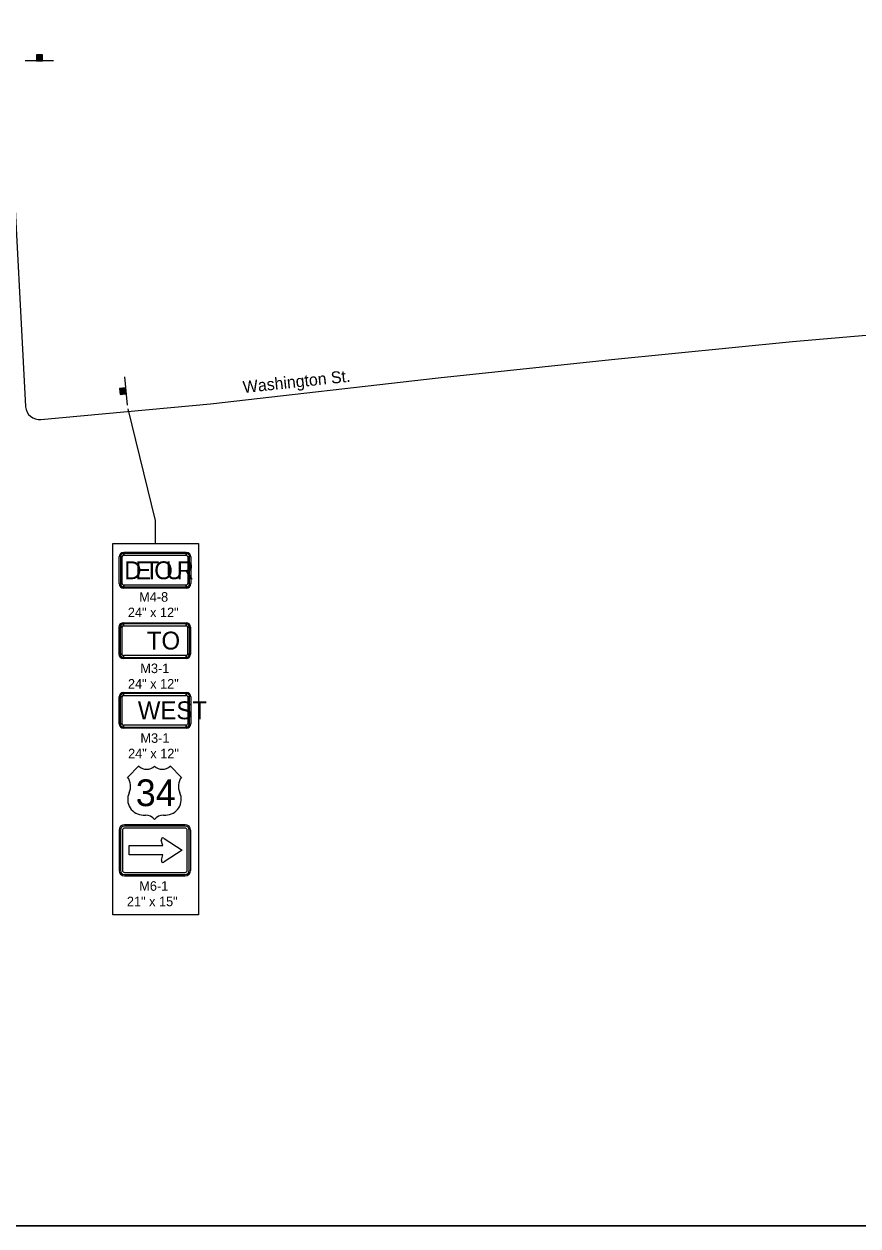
# Model space of a CAD drawing. Extents: x 10133 to 81668, y 6132 to 11018.
# Drawn here: x 10817 to 11517, y 7924 to 8934 of the extents above; entities that cross this region are included whole.
import ezdxf

# ---------------------------------------------------------------- set-up
doc = ezdxf.new("R2010")
doc.units = 0
for name, color, linetype in [('dsnTextFinalPlan', 7, 'Continuous'), ('Level 10', 7, 'Continuous'), ('Level 2', 7, 'Continuous'), ('Level 4', 7, 'Continuous'), ('Level 5', 7, 'Continuous'), ('SheetBorder', 7, 'Continuous'), ('SheetText', 7, 'Continuous')]:
    doc.layers.add(name, color=color, linetype=linetype)

msp = doc.modelspace()

# ---------------------------------------------------------------- linework, layer by layer
at = {"layer": 'dsnTextFinalPlan'}
for p, q in [((10841.4, 8903.1), (10817.4, 8903.1)), ((10832, 8907.8), (10827.1, 8907.8)), ((10827.1, 8907.5), (10832, 8907.5)), ((10832, 8907.3), (10827.1, 8907.3)), ((10827.1, 8907), (10832, 8907)), ((10832, 8906.8), (10827.1, 8906.8)), ((10827.1, 8906.4), (10832, 8906.4)), ((10832, 8906.3), (10827.1, 8906.3)), ((10827.1, 8905.9), (10832, 8905.9)), ((10832, 8905.6), (10827.1, 8905.5)), ((10827.1, 8905.3), (10832, 8905.3)), ((10832, 8905.1), (10827.1, 8905.1)), ((10827.1, 8904.8), (10832, 8904.9)), ((10832, 8904.6), (10827.1, 8904.6)), ((10827.1, 8904.4), (10832, 8904.4)), ((10832, 8904.2), (10827.1, 8904.2)), ((10827.1, 8903.9), (10832, 8904)), ((10832, 8903.7), (10827.1, 8903.7)), ((10827.1, 8903.5), (10832, 8903.5)), ((10900.9, 8637.6), (10903.2, 8613.7)), ((10897.2, 8627.7), (10897.7, 8622.8)), ((10897.9, 8622.9), (10897.5, 8627.7)), ((10897.7, 8627.7), (10898.1, 8622.9)), ((10898.4, 8622.9), (10897.9, 8627.8)), ((10898.1, 8627.8), (10898.6, 8622.9)), ((10899, 8623), (10898.5, 8627.8)), ((10898.7, 8627.8), (10899.2, 8623)), ((10899.5, 8623), (10899.1, 8627.9)), ((10899.4, 8627.9), (10899.9, 8623)), ((10900.1, 8623.1), (10899.7, 8627.9)), ((10899.9, 8627.9), (10900.3, 8623.1)), ((10900.6, 8623.1), (10900.1, 8628)), ((10900.4, 8628), (10900.9, 8623.1)), ((10901, 8623.2), (10900.6, 8628)), ((10900.7, 8628), (10901.2, 8623.2)), ((10901.5, 8623.2), (10901, 8628.1)), ((10901.2, 8628.1), (10901.7, 8623.2)), ((10901.9, 8623.2), (10901.5, 8628.1)), ((10830.8, 8601.8), (10973.3, 8615))]:
    msp.add_line(p, q, dxfattribs=at)
for points in [[(10785.1, 9142), (10794.6, 9051.1), (10817.8, 8612.5)], [(10973.3, 8615), (11164.6, 8636.6), (11310.1, 8652.1), (11462.4, 8667.2), (11586.1, 8678), (11684.7, 8691.3), (11805.7, 8706), (11965.7, 8718.9)], [(10927.1, 8497.6), (10927.1, 8516.9), (10904, 8610.6)]]:
    msp.add_lwpolyline(points, dxfattribs=at)
for points in [[(10827.1, 8903.2), (10832, 8903.2), (10832, 8908.1), (10827.1, 8908.1)], [(10902.2, 8623.3), (10901.7, 8628.2), (10896.8, 8627.7), (10897.3, 8622.8)], [(10891.1, 8497.6), (10963.2, 8497.6), (10963.2, 8185.4), (10891.1, 8185.4)], [(10891.1, 8497.6), (10963.2, 8497.6), (10963.2, 8185.4), (10891.1, 8185.4)]]:
    msp.add_lwpolyline(points, close=True, dxfattribs=at)
msp.add_arc((10829.7, 8613.7), 12, 185.8975, 275.3136, dxfattribs=at)
at = {"layer": 'Level 10'}
for p, q in [((10896.5, 8463.8), (10896.5, 8486.3)), ((10897.5, 8486.3), (10899, 8486.3)), ((10900.3, 8490.1), (10952.9, 8490.1)), ((10900.3, 8487.6), (10900.3, 8489.1)), ((10952.9, 8489.1), (10952.9, 8487.6)), ((10954.2, 8486.3), (10955.7, 8486.3)), ((10956.7, 8486.3), (10956.7, 8463.8)), ((10899, 8463.8), (10897.5, 8463.8)), ((10900.3, 8461), (10900.3, 8462.5)), ((10952.9, 8460), (10900.3, 8460)), ((10952.9, 8462.5), (10952.9, 8461)), ((10955.7, 8463.8), (10954.2, 8463.8)), ((10896.4, 8404.6), (10896.4, 8427.2)), ((10897.3, 8427.2), (10898.9, 8427.2)), ((10900.1, 8430.9), (10952.8, 8430.9)), ((10900.1, 8428.4), (10900.1, 8430)), ((10952.8, 8430), (10952.8, 8428.4)), ((10954, 8427.2), (10955.6, 8427.2)), ((10956.5, 8427.2), (10956.5, 8404.6)), ((10898.9, 8404.6), (10897.3, 8404.6)), ((10900.1, 8401.8), (10900.1, 8403.4)), ((10952.8, 8403.4), (10952.8, 8401.8)), ((10955.6, 8404.6), (10954, 8404.6)), ((10952.8, 8400.9), (10900.1, 8400.9)), ((10896.5, 8346.1), (10896.5, 8368.6)), ((10897.4, 8368.6), (10899, 8368.6)), ((10900.2, 8372.4), (10952.9, 8372.4)), ((10900.2, 8369.9), (10900.2, 8371.4)), ((10952.9, 8371.4), (10952.9, 8369.9)), ((10954.1, 8368.6), (10955.7, 8368.6)), ((10956.6, 8368.6), (10956.6, 8346.1)), ((10899, 8346.1), (10897.4, 8346.1)), ((10900.2, 8343.3), (10900.2, 8344.8)), ((10952.9, 8344.8), (10952.9, 8343.3)), ((10955.7, 8346.1), (10954.1, 8346.1)), ((10952.9, 8342.3), (10900.2, 8342.3)), ((10896.4, 8256.6), (10896.4, 8222.8)), ((10897.6, 8256.6), (10897.6, 8222.8)), ((10899.3, 8256.6), (10899.3, 8222.8)), ((10952, 8261.2), (10901, 8261.2)), ((10952, 8260.1), (10901, 8260.1)), ((10952, 8258.3), (10901, 8258.3)), ((10953.7, 8222.8), (10953.7, 8256.6)), ((10955.4, 8222.8), (10955.4, 8256.6)), ((10956.6, 8222.8), (10956.6, 8256.6)), ((10901, 8221.1), (10952, 8221.1)), ((10901, 8219.4), (10952, 8219.4)), ((10901, 8218.3), (10952, 8218.3))]:
    msp.add_line(p, q, dxfattribs=at)
for points in [[(10897.5, 8486.3), (10897.5, 8463.8), (10899, 8463.8), (10899, 8486.3), (10897.5, 8486.3)], [(10952.9, 8489.1), (10900.3, 8489.1), (10900.3, 8487.6), (10952.9, 8487.6), (10952.9, 8489.1)], [(10955.7, 8463.8), (10955.7, 8486.3), (10954.2, 8486.3), (10954.2, 8463.8), (10955.7, 8463.8)], [(10900.3, 8461), (10952.9, 8461), (10952.9, 8462.5), (10900.3, 8462.5), (10900.3, 8461)], [(10897.3, 8427.2), (10897.3, 8404.6), (10898.9, 8404.6), (10898.9, 8427.2), (10897.3, 8427.2)], [(10952.8, 8430), (10900.1, 8430), (10900.1, 8428.4), (10952.8, 8428.4), (10952.8, 8430)], [(10955.6, 8404.6), (10955.6, 8427.2), (10954, 8427.2), (10954, 8404.6), (10955.6, 8404.6)], [(10900.1, 8401.8), (10952.8, 8401.8), (10952.8, 8403.4), (10900.1, 8403.4), (10900.1, 8401.8)], [(10897.4, 8368.6), (10897.4, 8346.1), (10899, 8346.1), (10899, 8368.6), (10897.4, 8368.6)], [(10952.9, 8371.4), (10900.2, 8371.4), (10900.2, 8369.9), (10952.9, 8369.9), (10952.9, 8371.4)], [(10955.7, 8346.1), (10955.7, 8368.6), (10954.1, 8368.6), (10954.1, 8346.1), (10955.7, 8346.1)], [(10900.2, 8343.3), (10952.9, 8343.3), (10952.9, 8344.8), (10900.2, 8344.8), (10900.2, 8343.3)]]:
    msp.add_lwpolyline(points, close=True, dxfattribs=at)
for points in [[(10932, 8231.3), (10933.3, 8235.9), (10904.8, 8235.9), (10904.8, 8243.6), (10933.3, 8243.6), (10931.9, 8248.2)], [(10934.4, 8249.5), (10949.4, 8239.7), (10934.4, 8229.9)]]:
    msp.add_lwpolyline(points, dxfattribs=at)
for centre, radius, start, end in [((10900.3, 8486.3), 3.76, 90, 180), ((10900.3, 8486.3), 2.82, 90.0002, 179.9998), ((10900.3, 8486.3), 1.25, 90.0002, 179.9998), ((10952.9, 8486.3), 3.76, 0, 90), ((10952.9, 8486.3), 2.82, 0, 90.0002), ((10952.9, 8486.3), 1.25, 0, 90.0002), ((10900.3, 8463.8), 3.76, 180, 270), ((10900.3, 8463.8), 2.82, 179.9998, 270.0001), ((10900.3, 8463.8), 1.25, 179.9998, 270.0001), ((10952.9, 8463.8), 2.82, 270.0001, 0.0003), ((10952.9, 8463.8), 1.25, 270.0001, 0.0003), ((10952.9, 8463.8), 3.76, 270, 359.9911), ((10900.1, 8427.2), 3.76, 90, 180), ((10900.1, 8427.2), 2.82, 90.0002, 179.9998), ((10900.1, 8427.2), 1.25, 90.0002, 179.9998), ((10952.8, 8427.2), 3.76, 0, 90), ((10952.8, 8427.2), 2.82, 0, 90.0002), ((10952.8, 8427.2), 1.25, 0, 90.0002), ((10900.1, 8404.6), 3.76, 180, 270), ((10900.1, 8404.6), 2.82, 179.9998, 270.0001), ((10900.1, 8404.6), 1.25, 179.9998, 270.0001), ((10952.8, 8404.6), 2.82, 270.0001, 0.0003), ((10952.8, 8404.6), 1.25, 270.0001, 0.0003), ((10952.8, 8404.6), 3.76, 270, 359.9911), ((10900.2, 8368.6), 3.76, 90, 180), ((10900.2, 8368.6), 2.82, 90.0002, 179.9998), ((10900.2, 8368.6), 1.25, 90.0002, 179.9998), ((10952.9, 8368.6), 3.76, 0, 90), ((10952.9, 8368.6), 2.82, 0, 90.0002), ((10952.9, 8368.6), 1.25, 0, 90.0002), ((10900.2, 8346.1), 3.76, 180, 270), ((10900.2, 8346.1), 2.82, 179.9998, 270.0001), ((10900.2, 8346.1), 1.25, 179.9998, 270.0001), ((10952.9, 8346.1), 2.82, 270.0001, 0.0003), ((10952.9, 8346.1), 1.25, 270.0001, 0.0003), ((10952.9, 8346.1), 3.76, 270, 359.9911), ((10901, 8256.6), 4.58, 90, 180), ((10901, 8256.6), 3.44, 90, 180), ((10901, 8256.6), 1.72, 90, 180), ((10952, 8256.6), 4.58, 360, 90), ((10952, 8256.6), 3.44, 0, 90), ((10952, 8256.6), 1.72, 0, 90), ((10933.3, 8248.6), 1.43, 56.6109, 195.9691), ((11012.9, 8369.3), 143.2, 236.6109, 236.7714), ((10901, 8222.8), 4.58, 180, 270), ((10901, 8222.8), 3.44, 180, 270), ((10901, 8222.8), 1.72, 180, 270), ((10933.3, 8230.9), 1.4, 164.0309, 303.3104), ((11012.7, 8110.1), 143.2, 123.143, 123.3104), ((10952, 8222.8), 4.58, 270, 0), ((10952, 8222.8), 3.44, 270, 360), ((10952, 8222.8), 1.72, 270, 0)]:
    msp.add_arc(centre, radius, start, end, dxfattribs=at)
at = {"layer": 'Level 4'}
for p, q in [((10913.1, 8310.6), (10903.7, 8301.2)), ((10913.1, 8310.6), (10903.7, 8301.2)), ((10948.7, 8301.2), (10939.3, 8310.6)), ((10948.7, 8301.2), (10939.3, 8310.6)), ((10916.8, 8269.3), (10918.7, 8269.3)), ((10916.8, 8269.3), (10918.7, 8269.3)), ((10933.7, 8269.3), (10935.6, 8269.3)), ((10933.7, 8269.3), (10935.6, 8269.3))]:
    msp.add_line(p, q, dxfattribs=at)
for centre, radius, start, end in [((10919.6, 8317.2), 9.38, 225.5729, 314.4272), ((10919.6, 8317.2), 9.38, 225.5729, 314.4272), ((10932.8, 8317.2), 9.38, 225.5729, 314.4272), ((10932.8, 8317.2), 9.38, 225.5729, 314.4272), ((10893, 8293.5), 13.1, 334.9895, 35.6629), ((10893, 8293.5), 13.1, 334.9895, 35.6629), ((10959.4, 8293.5), 13.1, 144.3372, 205.01), ((10959.4, 8293.5), 13.1, 144.3372, 205.01), ((10916.8, 8282.4), 13.1, 154.9897, 270.0001), ((10916.8, 8282.4), 13.1, 154.9897, 270.0001), ((10935.6, 8282.4), 13.1, 270.0001, 25.0104), ((10935.6, 8282.4), 13.1, 270.0001, 25.0104), ((10918.7, 8259.9), 9.38, 36.8699, 90.0002), ((10918.7, 8259.9), 9.38, 36.8699, 90.0002), ((10933.7, 8259.9), 9.38, 90.0002, 143.13), ((10933.7, 8259.9), 9.38, 90.0002, 143.13)]:
    msp.add_arc(centre, radius, start, end, dxfattribs=at)
at = {"layer": 'SheetBorder'}
msp.add_lwpolyline([(10132.5, 9944), (13267.5, 9944), (13267.5, 7924), (10132.5, 7924)], close=True, dxfattribs=at)
at = {"layer": 'SheetText'}
msp.add_lwpolyline([(10132.5, 9944), (10132.5, 7924), (13267.5, 7924), (13267.5, 9944)], close=True, dxfattribs=at)

# ---------------------------------------------------------------- texts
at = {"layer": 'Level 10'}
for s, height, p in [('D', 15, (10900.8, 8467.5)), ('E', 15, (10910, 8467.5)), ('T', 15, (10917.8, 8467.5)), ('O', 15, (10926, 8467.5)), ('U', 15, (10935.6, 8467.5)), ('R', 15, (10944.8, 8467.5)), ('TO', 15.03, (10919.8, 8408.4)), ('WEST', 15.03, (10912.2, 8349.8))]:
    msp.add_text(s, height=height, dxfattribs=at).set_placement(p)
at = {"layer": 'Level 2'}
msp.add_text('Washington St.', height=10, rotation=6.0477, dxfattribs=at).set_placement((11001, 8623.9))
at = {"layer": 'Level 4'}
msp.add_text('34', height=22.5, dxfattribs=at).set_placement((10910.5, 8276.8))
msp.add_text('34', height=22.5, dxfattribs=at).set_placement((10910.5, 8276.8))
at = {"layer": 'Level 5'}
for s, p in [('M4-8', (10913.3, 8448.6)), ('24" x 12"', (10903.8, 8435.6)), ('M3-1', (10914.3, 8388.6)), ('24" x 12"', (10903.9, 8375.6)), ('M3-1', (10914.4, 8330)), ('24" x 12"', (10904, 8317)), ('M6-1', (10913.4, 8205.7)), ('21" x 15"', (10903, 8192.7))]:
    msp.add_text(s, height=8, dxfattribs=at).set_placement(p)

doc.saveas('drawing.dxf')
